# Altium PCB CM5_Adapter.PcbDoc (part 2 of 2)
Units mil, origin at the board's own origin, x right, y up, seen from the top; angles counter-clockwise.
Board outline 2180 x 1650 mil, 4 copper layers (Top Layer, Sig1, Sig2, Bottom Layer), stack 50.112 mil thick; 16 components, 251 nets, 1069 pads, 196 vias.
Unrouted connection lines stored in the file: 3.
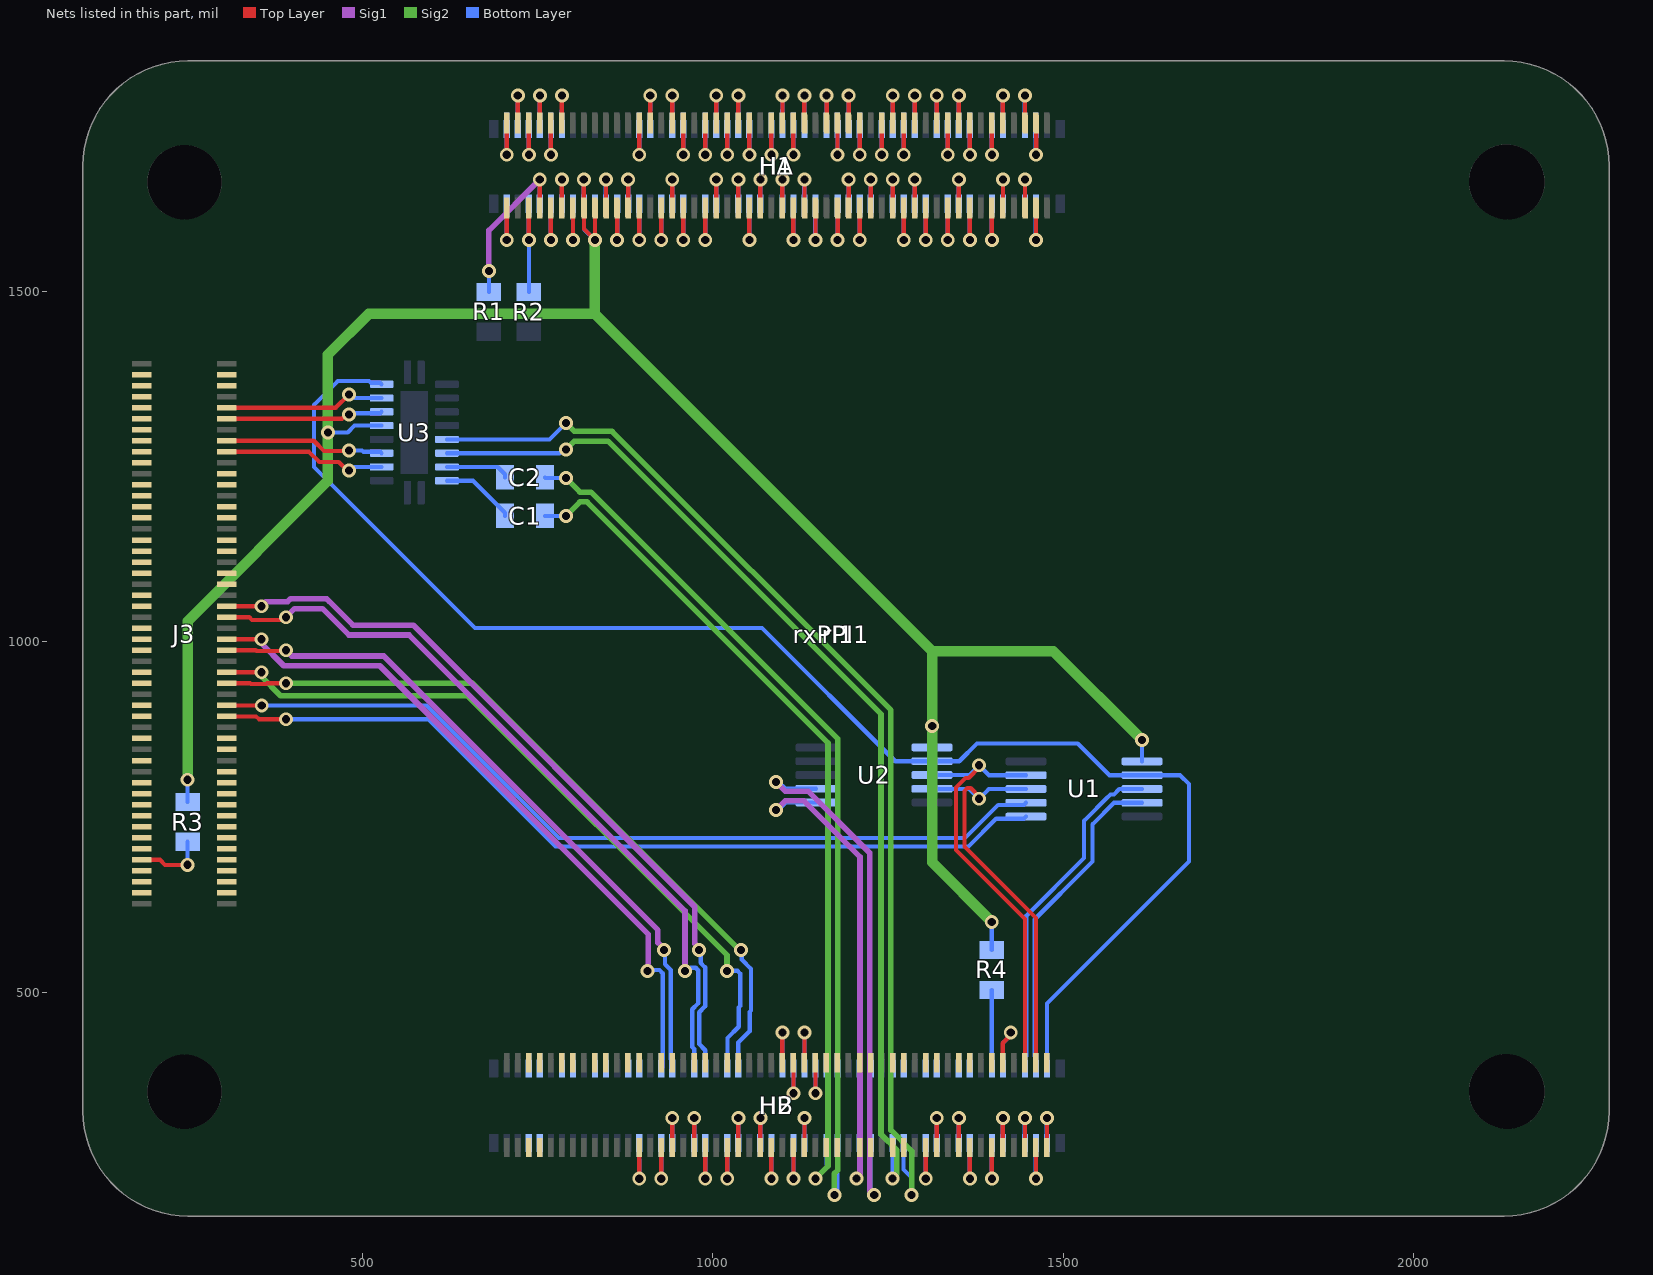
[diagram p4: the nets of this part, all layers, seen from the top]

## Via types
v1: diameter 19.68, hole 11.81, Top Layer to Bottom Layer, 196 vias

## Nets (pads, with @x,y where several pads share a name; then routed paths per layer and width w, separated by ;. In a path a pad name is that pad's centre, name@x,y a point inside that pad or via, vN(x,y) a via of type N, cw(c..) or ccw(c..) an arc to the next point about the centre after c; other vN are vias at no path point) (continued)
HDMI0_TX1_P: H2.76 HB.75 rPI1.176 rxPI1.176 | length 87.9
  Top Layer w6.3: v1(894.53,233.46) H2.76@894.53,276.9
  Bottom Layer w6.3: rPI1.176@894.34,277.83 894.34,260.9 894.53,260.72 v1(894.53,233.46)
HDMI0_TX2_N: H2.72 HB.71 rPI1.172 rxPI1.172 | length 87.9
  Top Layer w6.3: v1(926.02,233.46) H2.72@926.02,276.9
  Bottom Layer w6.3: rPI1.172@925.84,277.83 925.84,260.9 926.02,260.72 v1(926.02,233.46)
HDMI0_TX2_P: H2.70 HB.69 rPI1.170 rxPI1.170 | length 85.5
  Top Layer w6.3: H2.70@941.77,276.9 v1(941.77,320.08)
  Bottom Layer w6.3: rPI1.170@941.58,277.83 941.58,294.76 941.77,294.95 v1(941.77,320.08)
HDMI1_CEC: H2.49 HB.50 rPI1.149 rxPI1.149 | length 94.4
  Top Layer w6.3: H2.49@1099.06,399.09 1099.16,399.19 1099.16,442.03 v1(1099.25,442.13)
  Bottom Layer w6.3: HB.50@1099.25,390.88 v1(1099.25,442.13)
HDMI1_CLK_N: H2.66 HB.65 rPI1.166 rxPI1.166 | length 85.5
  Top Layer w6.3: H2.66@973.27,276.9 v1(973.27,320.08)
  Bottom Layer w6.3: rPI1.166@973.08,277.83 973.08,294.76 973.27,294.95 v1(973.27,320.08)
HDMI1_CLK_P: H2.64 HB.63 rPI1.164 rxPI1.164 | length 87.9
  Top Layer w6.3: v1(989.02,233.46) H2.64@989.02,276.9
  Bottom Layer w6.3: rPI1.164@988.83,277.83 988.83,260.9 989.02,260.72 v1(989.02,233.46)
HDMI1_HOTPLUG: H2.43 HB.44 rPI1.143 rxPI1.143 | length 79
  Top Layer w6.3: H2.43@1146.31,399.09 1146.4,399 1146.4,355.61 v1(1146.5,355.51)
  Bottom Layer w6.3: v1(1146.5,355.51) HB.44@1146.5,390.88
HDMI1_SCL: H2.47 HB.48 rPI1.147 rxPI1.147 | length 78
  Top Layer w6.3: v1(1115,355.51) H2.47@1115,398.16
  Bottom Layer w6.3: v1(1115,355.51) HB.48@1115,390.88
HDMI1_SDA: H2.45 HB.46 rPI1.145 rxPI1.145 | length 95.2
  Top Layer w6.3: H2.45@1130.75,398.16 v1(1130.75,442.13)
  Bottom Layer w6.3: HB.46@1130.75,390.88 v1(1130.75,442.13)
HDMI1_TX0_N: H2.60 HB.59 rPI1.160 rxPI1.160 | length 88.9
  Top Layer w6.3: H2.60@1020.32,277.83 1020.42,277.74 1020.42,233.56 v1(1020.51,233.46)
  Bottom Layer w6.3: rPI1.160@1020.32,277.83 1020.32,260.9 1020.51,260.72 v1(1020.51,233.46)
HDMI1_TX0_P: H2.58 HB.57 rPI1.158 rxPI1.158 | length 85.5
  Top Layer w6.3: H2.58@1036.26,276.9 v1(1036.26,320.08)
  Bottom Layer w6.3: rPI1.158@1036.07,277.83 1036.07,294.76 1036.26,294.95 v1(1036.26,320.08)
HDMI1_TX1_N: H2.54 HB.53 rPI1.154 rxPI1.154 | length 85.5
  Top Layer w6.3: H2.54@1067.76,276.9 v1(1067.76,320.08)
  Bottom Layer w6.3: rPI1.154@1067.57,277.83 1067.57,294.76 1067.76,294.95 v1(1067.76,320.08)
HDMI1_TX1_P: H2.52 HB.51 rPI1.152 rxPI1.152 | length 87.9
  Top Layer w6.3: v1(1083.5,233.46) H2.52@1083.5,276.9
  Bottom Layer w6.3: rPI1.152@1083.32,277.83 1083.32,260.9 1083.5,260.72 v1(1083.5,233.46)
HDMI1_TX2_N: H2.48 HB.47 rPI1.148 rxPI1.148 | length 94.2
  Top Layer w6.3: v1(1115,233.46) H2.48@1115,276.9
  Bottom Layer w6.3: v1(1115,233.46) HB.47@1115,284.18
HDMI1_TX2_P: H2.46 HB.45 rPI1.146 rxPI1.146 | length 79.1
  Top Layer w6.3: H2.46@1130.75,276.9 v1(1130.75,320.08)
  Bottom Layer w6.3: HB.45@1130.75,284.18 v1(1130.75,320.08)
I2C_SCL: J3.72 rxPI1.271
I2C_SDA: J3.70 rxPI1.269
NetC1_1: C1.1 U3.19 | length 106.5
  Bottom Layer w6: U3.19@620,1230.32 657.19,1230.32 703,1184.5 C1.1@703,1180
NetC2_1: C2.1 U3.18 | length 91.8
  Bottom Layer w6: U3.18@620,1250 692.56,1250 703,1239.56 C2.1@703,1235.06
NetH1_3: H1.3 HA.4 rPI1.3 rxPI1.3 | length 89.9
  Top Layer w6.3: v1(1461.46,1696.06) H1.3@1461.46,1739.81
  Bottom Layer w6.3: rPI1.3@1461.27,1742.17 1461.27,1696.25 v1(1461.46,1696.06)
NetH1_4: H1.4 HA.3 rPI1.4 rxPI1.4 | length 93.9
  Top Layer w6.3: rxPI1.4@1461.27,1620.91 1461.36,1620.81 1461.36,1574.11 v1(1461.46,1574.02)
  Bottom Layer w6.3: rPI1.4@1461.27,1620.91 1461.27,1574.2 v1(1461.46,1574.02)
NetH1_5: H1.5 HA.6 rPI1.5 rxPI1.5 | length 77.2
  Top Layer w6.3: rxPI1.5@1445.52,1742.17 1445.62,1742.26 1445.62,1780.62 v1(1445.71,1780.71)
  Bottom Layer w6.3: rPI1.5@1445.52,1742.17 1445.52,1780.52 v1(1445.71,1780.71)
NetH1_6: H1.6 HA.5 rPI1.6 rxPI1.6 | length 76.9
  Top Layer w6.3: H1.6@1445.71,1618.55 v1(1445.71,1660.63)
  Bottom Layer w6.3: HA.5@1445.71,1625.84 v1(1445.71,1660.63)
NetH1_9: H1.9 HA.10 rPI1.9 rxPI1.9 | length 77.2
  Top Layer w6.3: rxPI1.9@1414.03,1742.17 1414.12,1742.26 1414.12,1780.62 v1(1414.21,1780.71)
  Bottom Layer w6.3: rPI1.9@1414.03,1742.17 1414.03,1780.52 v1(1414.21,1780.71)
NetH1_10: H1.10 HA.9 rPI1.10 rxPI1.10 | length 76.9
  Top Layer w6.3: H1.10@1414.21,1618.55 v1(1414.21,1660.63)
  Bottom Layer w6.3: HA.9@1414.21,1625.84 v1(1414.21,1660.63)
NetH1_11: H1.11 HA.12 rPI1.11 rxPI1.11 | length 92.4
  Top Layer w6.3: rxPI1.11@1398.28,1742.17 1398.37,1742.07 1398.37,1696.16 v1(1398.46,1696.06)
  Bottom Layer w6.3: rPI1.11@1398.28,1742.17 1398.28,1696.25 v1(1398.46,1696.06)
NetH1_12: H1.12 HA.11 rPI1.12 rxPI1.12 | length 96.4
  Top Layer w6.3: v1(1398.46,1574.02) H1.12@1398.46,1618.55
  Bottom Layer w6.3: v1(1398.46,1574.02) HA.11@1398.46,1625.84
NetH1_15: H1.15 HA.16 rPI1.15 rxPI1.15 | length 80.2
  Top Layer w6.3: v1(1366.97,1696.06) H1.15@1366.97,1739.81
  Bottom Layer w6.3: v1(1366.97,1696.06) HA.16@1366.97,1732.53
NetH1_16: H1.16 HA.15 rPI1.16 rxPI1.16 | length 93.9
  Top Layer w6.3: rxPI1.16@1366.78,1620.91 1366.88,1620.81 1366.88,1574.11 v1(1366.97,1574.02)
  Bottom Layer w6.3: rPI1.16@1366.78,1620.91 1366.78,1574.2 v1(1366.97,1574.02)
NetH1_17: H1.17 HA.18 rPI1.17 rxPI1.17 | length 86.8
  Top Layer w6.3: rxPI1.17@1351.03,1742.17 1351.13,1742.26 1351.13,1780.62 v1(1351.22,1780.71)
  Bottom Layer w6.3: HA.18@1351.22,1732.53 v1(1351.22,1780.71)
NetH1_18: H1.18 HA.17 rPI1.18 rxPI1.18 | length 81.9
  Top Layer w6.3: H1.18@1351.22,1618.55 v1(1351.22,1660.63)
  Bottom Layer w6.3: rPI1.18@1351.03,1620.91 1351.03,1660.44 v1(1351.22,1660.63)
NetH1_19: H1.19 HA.20 rPI1.19 rxPI1.19 | length 89.9
  Top Layer w6.3: v1(1335.47,1696.06) H1.19@1335.47,1739.81
  Bottom Layer w6.3: rPI1.19@1335.29,1742.17 1335.29,1696.25 v1(1335.47,1696.06)
NetH1_20: H1.20 HA.19 rPI1.20 rxPI1.20 | length 91.5
  Top Layer w6.3: v1(1335.47,1574.02) H1.20@1335.47,1618.55
  Bottom Layer w6.3: rPI1.20@1335.29,1620.91 1335.29,1574.2 v1(1335.47,1574.02)
NetH1_21: H1.21 HA.22 rPI1.21 rxPI1.21 | length 77.2
  Top Layer w6.3: rxPI1.21@1319.54,1742.17 1319.63,1742.26 1319.63,1780.62 v1(1319.72,1780.71)
  Bottom Layer w6.3: rPI1.21@1319.54,1742.17 1319.54,1780.52 v1(1319.72,1780.71)
NetH1_24: H1.24 HA.23 rPI1.24 rxPI1.24 | length 91.5
  Top Layer w6.3: v1(1303.98,1574.02) H1.24@1303.98,1618.55
  Bottom Layer w6.3: rPI1.24@1303.79,1620.91 1303.79,1574.2 v1(1303.98,1574.02)
NetH1_25: H1.25 HA.26 rPI1.25 rxPI1.25 | length 76.7
  Top Layer w6.3: H1.25@1288.23,1742.35 v1(1288.23,1780.71)
  Bottom Layer w6.3: rPI1.25@1288.04,1742.17 1288.04,1759.1 ; 1288.23,1759.28 v1(1288.23,1780.71)
NetH1_26: H1.26 HA.25 rPI1.26 rxPI1.26 | length 79.6
  Top Layer w6.3: rxPI1.26@1288.04,1620.91 1288.13,1621 1288.13,1660.54 v1(1288.23,1660.63)
  Bottom Layer w6.3: rPI1.26@1288.04,1620.91 1288.04,1660.44 v1(1288.23,1660.63)
NetH1_27: H1.27 HA.28 rPI1.27 rxPI1.27 | length 92.4
  Top Layer w6.3: rxPI1.27@1272.29,1742.17 1272.39,1742.07 1272.39,1696.16 v1(1272.48,1696.06)
  Bottom Layer w6.3: rPI1.27@1272.29,1742.17 1272.29,1696.25 v1(1272.48,1696.06)
NetH1_28: H1.28 HA.27 rPI1.28 rxPI1.28 | length 91.5
  Top Layer w6.3: v1(1272.48,1574.02) H1.28@1272.48,1618.55
  Bottom Layer w6.3: rPI1.28@1272.29,1620.91 1272.29,1574.2 v1(1272.48,1574.02)
NetH1_29: H1.29 HA.30 rPI1.29 rxPI1.29 | length 76.7
  Top Layer w6.3: H1.29@1256.73,1742.35 v1(1256.73,1780.71)
  Bottom Layer w6.3: rPI1.29@1256.54,1742.17 1256.55,1759.1 ; 1256.73,1759.28 v1(1256.73,1780.71)
NetH1_30: H1.30 HA.29 rPI1.30 rxPI1.30 | length 79.6
  Top Layer w6.3: rxPI1.30@1256.55,1620.91 1256.64,1621 1256.64,1660.54 v1(1256.73,1660.63)
  Bottom Layer w6.3: rPI1.30@1256.54,1620.91 1256.55,1660.44 v1(1256.73,1660.63)
NetH1_31: H1.31 HA.32 rPI1.31 rxPI1.31 | length 92.4
  Top Layer w6.3: rxPI1.31@1240.8,1742.17 1240.89,1742.07 1240.89,1696.16 v1(1240.98,1696.06)
  Bottom Layer w6.3: rPI1.31@1240.8,1742.17 1240.8,1696.25 v1(1240.98,1696.06)
NetH1_34: H1.34 HA.33 rPI1.34 rxPI1.34 | length 81.9
  Top Layer w6.3: H1.34@1225.24,1618.55 v1(1225.24,1660.63)
  Bottom Layer w6.3: rPI1.34@1225.05,1620.91 1225.05,1660.44 v1(1225.24,1660.63)
NetH1_35: H1.35 HA.36 rPI1.35 rxPI1.35 | length 82.6
  Top Layer w6.3: rxPI1.35@1209.3,1742.17 1209.39,1742.07 1209.39,1696.16 v1(1209.49,1696.06)
  Bottom Layer w6.3: v1(1209.49,1696.06) HA.36@1209.49,1732.53
NetH1_36: H1.36 HA.35 rPI1.36 rxPI1.36 | length 93.9
  Top Layer w6.3: rxPI1.36@1209.3,1620.91 1209.39,1620.81 1209.39,1574.11 v1(1209.49,1574.02)
  Bottom Layer w6.3: rPI1.36@1209.3,1620.91 1209.3,1574.2 v1(1209.49,1574.02)
NetH1_37: H1.37 HA.38 rPI1.37 rxPI1.37 | length 86.8
  Top Layer w6.3: rxPI1.37@1193.55,1742.17 1193.65,1742.26 1193.65,1780.62 v1(1193.74,1780.71)
  Bottom Layer w6.3: HA.38@1193.74,1732.53 v1(1193.74,1780.71)
NetH1_38: H1.38 HA.37 rPI1.38 rxPI1.38 | length 79.6
  Top Layer w6.3: rxPI1.38@1193.55,1620.91 1193.65,1621 1193.65,1660.54 v1(1193.74,1660.63)
  Bottom Layer w6.3: rPI1.38@1193.55,1620.91 1193.55,1660.44 v1(1193.74,1660.63)
NetH1_39: H1.39 HA.40 rPI1.39 rxPI1.39 | length 92.4
  Top Layer w6.3: rxPI1.39@1177.81,1742.17 1177.9,1742.07 1177.9,1696.16 v1(1177.99,1696.06)
  Bottom Layer w6.3: rPI1.39@1177.8,1742.17 1177.81,1696.25 v1(1177.99,1696.06)
NetH1_40: H1.40 HA.39 rPI1.40 rxPI1.40 | length 91.5
  Top Layer w6.3: v1(1177.99,1574.02) H1.40@1177.99,1618.55
  Bottom Layer w6.3: rPI1.40@1177.8,1620.91 1177.81,1574.2 v1(1177.99,1574.02)
NetH1_41: H1.41 HA.42 rPI1.41 rxPI1.41 | length 89.1
  Top Layer w6.3: H1.41@1162.24,1739.81 v1(1162.24,1780.71)
  Bottom Layer w6.3: HA.42@1162.24,1732.53 v1(1162.24,1780.71)
NetH1_44: H1.44 HA.43 rPI1.44 rxPI1.44 | length 93.9
  Top Layer w6.3: rxPI1.44@1146.31,1620.91 1146.4,1620.81 1146.4,1574.11 v1(1146.5,1574.02)
  Bottom Layer w6.3: rPI1.44@1146.31,1620.91 1146.31,1574.2 v1(1146.5,1574.02)
NetH1_45: H1.45 HA.46 rPI1.45 rxPI1.45 | length 76.7
  Top Layer w6.3: H1.45@1130.56,1742.35 v1(1130.56,1780.71)
  Bottom Layer w6.3: rPI1.45@1130.37,1742.17 1130.37,1759.1 ; 1130.56,1759.28 v1(1130.56,1780.71)
NetH1_46: H1.46 HA.45 rPI1.46 rxPI1.46 | length 81.9
  Top Layer w6.3: H1.46@1130.75,1618.55 v1(1130.75,1660.63)
  Bottom Layer w6.3: rPI1.46@1130.56,1620.91 1130.56,1660.44 v1(1130.75,1660.63)
NetH1_47: H1.47 HA.48 rPI1.47 rxPI1.47 | length 82.7
  Top Layer w6.3: rxPI1.47@1114.81,1742.17 1114.91,1742.07 1114.91,1696.16 v1(1115,1696.06)
  Bottom Layer w6.3: rPI1.47@1114.81,1732.53 1114.81,1696.25 v1(1115,1696.06)
NetH1_48: H1.48 HA.47 rPI1.48 rxPI1.48 | length 93.9
  Top Layer w6.3: rxPI1.48@1114.81,1620.91 1114.91,1620.81 1114.91,1574.11 v1(1115,1574.02)
  Bottom Layer w6.3: rPI1.48@1114.81,1620.91 1114.81,1574.2 v1(1115,1574.02)
NetH1_49: H1.49 HA.50 rPI1.49 rxPI1.49 | length 76.7
  Top Layer w6.3: H1.49@1099.25,1742.35 v1(1099.25,1780.71)
  Bottom Layer w6.3: rPI1.49@1099.06,1742.17 1099.06,1759.1 ; 1099.25,1759.28 v1(1099.25,1780.71)
NetH1_50: H1.50 HA.49 rPI1.50 rxPI1.50 | length 79.6
  Top Layer w6.3: rxPI1.50@1099.06,1620.91 1099.16,1621 1099.16,1660.54 v1(1099.25,1660.63)
  Bottom Layer w6.3: rPI1.50@1099.06,1620.91 1099.06,1637.84 1099.25,1638.02 v1(1099.25,1660.63)
NetH1_51: H1.51 HA.52 rPI1.51 rxPI1.51 | length 92.4
  Top Layer w6.3: rxPI1.51@1083.32,1742.17 1083.41,1742.07 1083.41,1696.16 v1(1083.5,1696.06)
  Bottom Layer w6.3: rPI1.51@1083.32,1742.17 1083.32,1725.24 1083.5,1725.05 v1(1083.5,1696.06)
NetH1_54: H1.54 HA.53 rPI1.54 rxPI1.54 | length 79.6
  Top Layer w6.3: rxPI1.54@1067.57,1620.91 1067.66,1621 1067.66,1660.54 v1(1067.76,1660.63)
  Bottom Layer w6.3: rPI1.54@1067.57,1620.91 1067.57,1637.84 1067.76,1638.02 v1(1067.76,1660.63)
NetH1_55: H1.55 HA.56 rPI1.55 rxPI1.55 | length 80.2
  Top Layer w6.3: v1(1052.01,1696.06) H1.55@1052.01,1739.81
  Bottom Layer w6.3: v1(1052.01,1696.06) HA.56@1052.01,1732.53
NetH1_56: H1.56 HA.55 rPI1.56 rxPI1.56 | length 93.9
  Top Layer w6.3: rxPI1.56@1051.82,1620.91 1051.91,1620.81 1051.91,1574.11 v1(1052.01,1574.02)
  Bottom Layer w6.3: rPI1.56@1051.82,1620.91 1051.82,1603.98 1052.01,1603.79 v1(1052.01,1574.02)
NetH1_57: H1.57 HA.58 rPI1.57 rxPI1.57 | length 89.1
  Top Layer w6.3: H1.57@1036.26,1739.81 v1(1036.26,1780.71)
  Bottom Layer w6.3: HA.58@1036.26,1732.53 v1(1036.26,1780.71)
NetH1_58: H1.58 HA.57 rPI1.58 rxPI1.58 | length 79.6
  Top Layer w6.3: rxPI1.58@1036.07,1620.91 1036.17,1621 1036.17,1660.54 v1(1036.26,1660.63)
  Bottom Layer w6.3: rPI1.58@1036.07,1620.91 1036.07,1637.84 1036.26,1638.02 v1(1036.26,1660.63)
NetH1_59: H1.59 HA.60 rPI1.59 rxPI1.59 | length 82.6
  Top Layer w6.3: rxPI1.59@1020.32,1742.17 1020.42,1742.07 1020.42,1696.16 v1(1020.51,1696.06)
  Bottom Layer w6.3: v1(1020.51,1696.06) HA.60@1020.51,1732.53
NetH1_61: H1.61 HA.62 rPI1.61 rxPI1.61 | length 89.1
  Top Layer w6.3: H1.61@1004.76,1739.81 v1(1004.76,1780.71)
  Bottom Layer w6.3: HA.62@1004.76,1732.53 v1(1004.76,1780.71)
NetH1_62: H1.62 HA.61 rPI1.62 rxPI1.62 | length 81.9
  Top Layer w6.3: H1.62@1004.76,1618.55 v1(1004.76,1660.63)
  Bottom Layer w6.3: rPI1.62@1004.58,1620.91 1004.58,1637.84 1004.76,1638.02 v1(1004.76,1660.63)
NetH1_63: H1.63 HA.64 rPI1.63 rxPI1.63 | length 82.6
  Top Layer w6.3: rxPI1.63@988.83,1742.17 988.92,1742.07 988.92,1696.16 v1(989.02,1696.06)
  Bottom Layer w6.3: v1(989.02,1696.06) HA.64@989.02,1732.53
NetH1_64: H1.64 HA.63 rPI1.64 rxPI1.64 | length 91.5
  Top Layer w6.3: v1(989.02,1574.02) H1.64@989.02,1618.55
  Bottom Layer w6.3: rPI1.64@988.83,1620.91 988.83,1603.98 989.02,1603.79 v1(989.02,1574.02)
NetH1_67: H1.67 HA.68 rPI1.67 rxPI1.67 | length 82.6
  Top Layer w6.3: rxPI1.67@957.33,1742.17 957.43,1742.07 957.43,1696.16 v1(957.52,1696.06)
  Bottom Layer w6.3: v1(957.52,1696.06) HA.68@957.52,1732.53
NetH1_68: H1.68 HA.67 rPI1.68 rxPI1.68 | length 98.8
  Top Layer w6.3: rxPI1.68@957.33,1620.91 957.43,1620.81 957.43,1574.11 v1(957.52,1574.02)
  Bottom Layer w6.3: v1(957.52,1574.02) HA.67@957.52,1625.84
NetH1_69: H1.69 HA.70 rPI1.69 rxPI1.69 | length 89.1
  Top Layer w6.3: H1.69@941.77,1739.81 v1(941.77,1780.71)
  Bottom Layer w6.3: HA.70@941.77,1732.53 v1(941.77,1780.71)
NetH1_70: H1.70 HA.69 rPI1.70 rxPI1.70 | length 76.9
  Top Layer w6.3: H1.70@941.77,1618.55 v1(941.77,1660.63)
  Bottom Layer w6.3: HA.69@941.77,1625.84 v1(941.77,1660.63)
NetH1_72: H1.72 HA.71 rPI1.72 rxPI1.72 | length 91.5
  Top Layer w6.3: v1(926.02,1574.02) H1.72@926.02,1618.55
  Bottom Layer w6.3: rPI1.72@925.84,1620.91 925.84,1603.98 926.02,1603.79 v1(926.02,1574.02)
NetH1_73: H1.73 HA.74 rPI1.73 rxPI1.73 | length 77.2
  Top Layer w6.3: rxPI1.73@910.09,1742.17 910.18,1742.26 910.18,1780.62 v1(910.28,1780.71)
  Bottom Layer w6.3: rPI1.73@910.09,1742.17 910.09,1759.1 910.28,1759.28 v1(910.28,1780.71)
NetH1_75: H1.75 HA.76 rPI1.75 rxPI1.75 | length 92.4
  Top Layer w6.3: rxPI1.75@894.34,1742.17 894.43,1742.07 894.43,1696.16 v1(894.53,1696.06)
  Bottom Layer w6.3: rPI1.75@894.34,1742.17 894.34,1725.24 894.53,1725.05 v1(894.53,1696.06)
NetH1_76: H1.76 HA.75 rPI1.76 rxPI1.76 | length 98.8
  Top Layer w6.3: rxPI1.76@894.34,1620.91 894.43,1620.81 894.43,1574.11 v1(894.53,1574.02)
  Bottom Layer w6.3: v1(894.53,1574.02) HA.75@894.53,1625.84
NetH1_78: H1.78 HA.77 rPI1.78 rxPI1.78 | length 79.6
  Top Layer w6.3: rxPI1.78@878.59,1620.91 878.69,1621 878.69,1660.54 v1(878.78,1660.63)
  Bottom Layer w6.3: rPI1.78@878.59,1620.91 878.59,1637.84 878.78,1638.02 v1(878.78,1660.63)
NetH1_80: H1.80 HA.79 rPI1.80 rxPI1.80 | length 96.4
  Top Layer w6.3: v1(863.03,1574.02) H1.80@863.03,1618.55
  Bottom Layer w6.3: v1(863.03,1574.02) HA.79@863.03,1625.84
NetH1_82: H1.82 HA.81 rPI1.82 rxPI1.82 | length 81.9
  Top Layer w6.3: v1(847.1,1660.63) 847.19,1660.54 847.19,1618.65 H1.82@847.28,1618.55
  Bottom Layer w6.3: rPI1.82@847.1,1620.91 v1(847.1,1660.63)
NetH1_88: H1.88 HA.87 rPI1.88 rxPI1.88 | length 91.5
  Top Layer w6.3: v1(800.04,1574.02) H1.88@800.04,1618.55
  Bottom Layer w6.3: rPI1.88@799.85,1620.91 799.85,1603.98 800.04,1603.79 v1(800.04,1574.02)
NetH1_89: H1.89 HA.90 rPI1.89 rxPI1.89 | length 77.2
  Top Layer w6.3: rxPI1.89@784.1,1742.17 784.2,1742.26 784.2,1780.62 v1(784.29,1780.71)
  Bottom Layer w6.3: rPI1.89@784.1,1742.17 784.1,1759.1 784.29,1759.28 v1(784.29,1780.71)
NetH1_90: H1.90 HA.89 rPI1.90 rxPI1.90 | length 79.6
  Top Layer w6.3: rxPI1.90@784.1,1620.91 784.2,1621 784.2,1660.54 v1(784.29,1660.63)
  Bottom Layer w6.3: rPI1.90@784.1,1620.91 784.1,1637.84 784.29,1638.02 v1(784.29,1660.63)
NetH1_91: H1.91 HA.92 rPI1.91 rxPI1.91 | length 89.9
  Top Layer w6.3: v1(768.54,1696.06) H1.91@768.54,1739.81
  Bottom Layer w6.3: rPI1.91@768.36,1742.17 768.36,1725.24 768.54,1725.05 v1(768.54,1696.06)
NetH1_92: H1.92 HA.91 rPI1.92 rxPI1.92 | length 93.9
  Top Layer w6.3: rxPI1.92@768.36,1620.91 768.45,1620.81 768.45,1574.11 v1(768.54,1574.02)
  Bottom Layer w6.3: rPI1.92@768.36,1620.91 768.36,1603.98 768.54,1603.79 v1(768.54,1574.02)
NetH1_93: H1.93 HA.94 rPI1.93 rxPI1.93 | length 77.2
  Top Layer w6.3: rxPI1.93@752.61,1742.17 752.7,1742.26 752.7,1780.62 v1(752.8,1780.71)
  Bottom Layer w6.3: rPI1.93@752.61,1742.17 752.61,1759.1 752.8,1759.28 v1(752.8,1780.71)
NetH1_94: H1.94 HA.93 R1.1 rPI1.94 rxPI1.94 | length 270.2
  Top Layer w6.3: rxPI1.94@752.61,1620.91 v1(752.61,1660.63)
  Sig1 w8: v1(679.96,1530) 679.96,1587.98 v1(752.61,1660.63)
  Bottom Layer w6: R1.1@679.96,1500 v1(679.96,1530)
  Bottom Layer w6.3: rPI1.94@752.61,1620.91 v1(752.61,1660.63)
NetH1_95: H1.95 HA.96 rPI1.95 rxPI1.95 | length 92.4
  Top Layer w6.3: rxPI1.95@736.86,1742.17 736.95,1742.07 736.95,1696.16 v1(737.05,1696.06)
  Bottom Layer w6.3: rPI1.95@736.86,1742.17 736.86,1725.24 737.05,1725.05 v1(737.05,1696.06)
NetH1_96: H1.96 HA.95 R2.1 rPI1.96 rxPI1.96 | length 168
  Top Layer w6.3: rxPI1.96@736.86,1620.91 736.95,1620.81 736.95,1574.11 v1(737.05,1574.02)
  Bottom Layer w6: R2.1@737.05,1500 v1(737.05,1574.02)
  Bottom Layer w6.3: rPI1.96@736.86,1620.91 736.86,1603.98 737.05,1603.79 v1(737.05,1574.02)
NetH1_97: H1.97 HA.98 rPI1.97 rxPI1.97 | length 76.7
  Top Layer w6.3: H1.97@721.3,1742.35 v1(721.3,1780.71)
  Bottom Layer w6.3: rPI1.97@721.11,1742.17 721.11,1759.1 ; 721.3,1759.28 v1(721.3,1780.71)
NetH1_99: H1.99 HA.100 rPI1.99 rxPI1.99 | length 92.4
  Top Layer w6.3: rxPI1.99@705.36,1742.17 705.46,1742.07 705.46,1696.16 v1(705.55,1696.06)
  Bottom Layer w6.3: rPI1.99@705.36,1742.17 705.36,1725.24 705.55,1725.05 v1(705.55,1696.06)
NetH1_100: H1.100 HA.99 rPI1.100 rxPI1.100 | length 93.9
  Top Layer w6.3: rxPI1.100@705.36,1620.91 705.46,1620.81 705.46,1574.11 v1(705.55,1574.02)
  Bottom Layer w6.3: rPI1.100@705.36,1620.91 705.36,1603.98 705.55,1603.79 v1(705.55,1574.02)
NetH2_11: H2.11 rxPI1.111
NetH2_15: H2.15 rxPI1.115
NetH2_17: H2.17 rxPI1.117
NetH2_21: H2.21 rxPI1.121
NetH2_23: H2.23 rxPI1.123
NetH2_27: H2.27 rxPI1.127
NetH2_28: H2.28 rxPI1.128
NetH2_29: H2.29 rxPI1.129
NetH2_30: H2.30 rxPI1.130
NetH2_33: H2.33 rxPI1.133
NetH2_34: H2.34 rxPI1.134
NetH2_35: H2.35 rxPI1.135
NetH2_36: H2.36 rxPI1.136
NetH2_39: H2.39 rxPI1.139
NetH2_40: H2.40 rxPI1.140
NetH2_41: H2.41 rxPI1.141
NetH2_42: H2.42 rxPI1.142
NetH2_57: H2.57 rxPI1.157
NetH2_59: H2.59 rxPI1.159
NetH2_63: H2.63 rxPI1.163
NetH2_65: H2.65 rxPI1.165
NetH2_69: H2.69 rxPI1.169
NetH2_71: H2.71 rxPI1.171
NetH2_75: H2.75 rxPI1.175
NetH2_77: H2.77 rxPI1.177
NetH2_81: H2.81 rxPI1.181
NetH2_83: H2.83 rxPI1.183
NetH2_87: H2.87 rxPI1.187
NetH2_89: H2.89 rxPI1.189
NetH2_93: H2.93 rxPI1.193
NetH2_94: H2.94 rxPI1.194
NetH2_95: H2.95 rxPI1.195
NetH2_96: H2.96 rxPI1.196
NetHB_12: HB.12 R4.2 rPI1.111 | length 103.9
  Bottom Layer w6: rPI1.111@1398.28,399.09 R4.2@1398.28,503
NetHB_16: HB.16 rPI1.115
NetHB_18: HB.18 rPI1.117
NetHB_22: HB.22 rPI1.121
NetHB_24: HB.24 rPI1.123
NetHB_28: HB.28 rPI1.127
NetHB_30: HB.30 rPI1.129
NetHB_34: HB.34 rPI1.133
NetHB_36: HB.36 rPI1.135
NetHB_40: HB.40 rPI1.139
NetHB_42: HB.42 rPI1.141
NetHB_76: HB.76 rPI1.175
NetHB_78: HB.78 rPI1.177
NetHB_82: HB.82 rPI1.181
NetHB_84: HB.84 rPI1.183
NetHB_88: HB.88 rPI1.187
NetHB_90: HB.90 rPI1.189
NetHB_93: HB.93 rPI1.194
NetHB_94: HB.94 rPI1.193
NetHB_95: HB.95 rPI1.196
NetHB_96: HB.96 rPI1.195
NetJ3_3: J3.3 rxPI1.204
NetJ3_4: J3.4 rxPI1.203
NetJ3_5: J3.5 rxPI1.206
NetJ3_6: J3.6 rxPI1.205
NetJ3_7: J3.7 rxPI1.208
NetJ3_9: J3.9 rxPI1.210
NetJ3_11: J3.11 rxPI1.212
NetJ3_13: J3.13 rxPI1.214
NetJ3_15: J3.15 rxPI1.216
NetJ3_17: J3.17 rxPI1.218
NetJ3_19: J3.19 rxPI1.220
NetJ3_22: J3.22 rxPI1.221
NetJ3_23: J3.23 rxPI1.224
NetJ3_24: J3.24 rxPI1.223
NetJ3_25: J3.25 rxPI1.226
NetJ3_27: J3.27 rxPI1.228
NetJ3_28: J3.28 rxPI1.227
NetJ3_29: J3.29 rxPI1.230
NetJ3_30: J3.30 rxPI1.229
NetJ3_33: J3.33 rxPI1.234
NetJ3_34: J3.34 rxPI1.233
NetJ3_35: J3.35 rxPI1.236
NetJ3_36: J3.36 rxPI1.235
NetJ3_37: J3.37 rxPI1.238
NetJ3_39: J3.39 rxPI1.240
NetJ3_40: J3.40 rxPI1.239
NetJ3_42: J3.42 rxPI1.241
NetJ3_43: J3.43 rxPI1.244
NetJ3_45: J3.45 rxPI1.246
NetJ3_49: J3.49 rxPI1.250
NetJ3_51: J3.51 rxPI1.252
NetJ3_53: J3.53 rxPI1.254
NetJ3_57: J3.57 rxPI1.258
NetJ3_59: J3.59 rxPI1.260
NetJ3_63: J3.63 rxPI1.264
NetJ3_65: J3.65 rxPI1.266
NetJ3_69: J3.69 rxPI1.270
NetJ3_73: J3.73 rxPI1.274
NetJ3_76: J3.76 rxPI1.275
NetJ3_77: J3.77 rxPI1.278
NetJ3_78: J3.78 rxPI1.277
NetJ3_79: J3.79 rxPI1.280
NetJ3_80: J3.80 rxPI1.279
NetJ3_81: J3.81 rxPI1.282
NetJ3_82: J3.82 rxPI1.281
NetJ3_83: J3.83 rxPI1.284
NetJ3_84: J3.84 rxPI1.283
NetJ3_85: J3.85 rxPI1.286
NetJ3_86: J3.86 rxPI1.285
NetJ3_87: J3.87 rxPI1.288
NetJ3_88: J3.88 rxPI1.287
NetJ3_89: J3.89 rxPI1.290
NetJ3_90: J3.90 rxPI1.289
NetJ3_91: J3.91 R3.2 rxPI1.292 | length 99.7
  Top Layer w6: J3.91@184.13,688.95 210,688.95 217.32,681.62 v1@247.81,681.62
  Bottom Layer w6: v1(249.47,681.62) R3.2@249.47,714.62
NetJ3_92: J3.92 rxPI1.291
NetJ3_93: J3.93 rxPI1.294
NetJ3_94: J3.94 rxPI1.293
NetJ3_95: J3.95 rxPI1.296
NetJ3_96: J3.96 rxPI1.295
NetJ3_97: J3.97 rxPI1.298
NetJ3_98: J3.98 rxPI1.297
PCIe_CLK_N: H2.12 HB.11 rPI1.112 rxPI1.112 | length 88.9
  Top Layer w6.3: H2.12@1398.28,277.83 1398.37,277.74 1398.37,233.56 v1(1398.46,233.46)
  Bottom Layer w6.3: rPI1.112@1398.28,277.83 1398.28,233.65 v1(1398.46,233.46)
PCIe_CLK_nREQ: H2.2 HB.1 rPI1.102 rxPI1.102 | length 84.6
  Top Layer w6.3: H2.2@1477.02,277.83 1477.11,277.93 1477.11,319.99 v1(1477.2,320.08)
  Bottom Layer w6.3: rPI1.102@1477.02,277.83 1477.02,319.89 v1(1477.2,320.08)
PCIe_CLK_P: H2.10 HB.9 rPI1.110 rxPI1.110 | length 84.6
  Top Layer w6.3: H2.10@1414.03,277.83 1414.12,277.93 1414.12,319.99 v1(1414.21,320.08)
  Bottom Layer w6.3: rPI1.110@1414.03,277.83 1414.03,319.89 v1(1414.21,320.08)
PCIe_nRST: H2.9 HB.10 rPI1.109 rxPI1.109 | length 95.5
  Top Layer w6.3: H2.9@1414.12,399.19 1414.03,399.28 1414.03,427.1 1425.43,438.5 v1(1425.43,442.13)
  Bottom Layer w6.3: rPI1.109@1414.03,399.09 1414.21,399.28 1414.21,427.28 1425.43,438.5 v1(1425.43,442.13)
PCIe_RX_N: H2.18 HB.17 rPI1.118 rxPI1.118 | length 84.6
  Top Layer w6.3: H2.18@1351.03,277.83 1351.13,277.93 1351.13,319.99 v1(1351.22,320.08)
  Bottom Layer w6.3: rPI1.118@1351.03,277.83 1351.03,319.89 v1(1351.22,320.08)
PCIe_RX_P: H2.16 HB.15 rPI1.116 rxPI1.116 | length 88.9
  Top Layer w6.3: H2.16@1366.78,277.83 1366.88,277.74 1366.88,233.56 v1(1366.97,233.46)
  Bottom Layer w6.3: rPI1.116@1366.78,277.83 1366.78,233.65 v1(1366.97,233.46)
PCIe_TX_N: H2.24 HB.23 rPI1.124 rxPI1.124 | length 88.9
  Top Layer w6.3: H2.24@1303.79,277.83 1303.88,277.74 1303.88,233.56 v1(1303.98,233.46)
  Bottom Layer w6.3: rPI1.124@1303.79,277.83 1303.79,233.65 v1(1303.98,233.46)
PCIe_TX_P: H2.22 HB.21 rPI1.122 rxPI1.122 | length 84.6
  Top Layer w6.3: H2.22@1319.54,277.83 1319.63,277.93 1319.63,319.99 v1(1319.72,320.08)
  Bottom Layer w6.3: rPI1.122@1319.54,277.83 1319.54,319.89 v1(1319.72,320.08)
Res104: H2.4 HB.3 rPI1.104 rxPI1.104 | length 88.9
  Top Layer w6.3: H2.4@1461.27,277.83 1461.36,277.74 1461.36,233.56 v1(1461.46,233.46)
  Bottom Layer w6.3: rPI1.104@1461.27,277.83 1461.27,233.65 v1(1461.46,233.46)
Res106: H2.6 HB.5 rPI1.106 rxPI1.106 | length 84.6
  Top Layer w6.3: H2.6@1445.52,277.83 1445.62,277.93 1445.62,319.99 v1(1445.71,320.08)
  Bottom Layer w6.3: rPI1.106@1445.52,277.83 1445.52,319.89 v1(1445.71,320.08)
USB20_HOST_D_N: J3.66 rxPI1.265 U1.6 | length 1236.3
  Top Layer w6: J3.66@305.39,893.67 347.43,893.67 351.36,889.73 v1(390,889.73)
  Bottom Layer w6: v1(390,889.73) 593.29,889.73 775.03,708 1365.01,708 1404.64,747.63 1444.13,747.63 U1.6@1447.13,750.63
USB20_HOST_D_P: J3.64 rxPI1.263 U1.7 | length 1241
  Top Layer w6: J3.64@305.39,909.42 v1(355.5,909.42)
  Bottom Layer w6: v1(355.5,909.42) 590.58,909.42 780,720 1360.04,720 1407.35,767.32 1444.13,767.32 U1.7@1447.13,770.32
USB30_D_N: HB.35 rPI1.136 U2.6 | length 727.5
  Sig1 w8: v1(1090,760) 1103,773 1130,773 1210,693 1210,238.69 v1(1204.96,233.65)
  Bottom Layer w6: v1(1090,760) 1093.7,760 1104.33,770.63 U2.6@1147.13,770.63 ; v1(1204.96,233.65) 1204.96,237.35 1209.3,241.7 rPI1.136@1209.3,277.83
USB30_D_P: HB.33 rPI1.134 U2.7 | length 798.4
  Sig1 w8: v1(1090,800) 1103,787 1135.8,787 1224,698.8 1224,216.16 v1(1230.16,210)
  Bottom Layer w6: v1(1090,800) 1093.7,800 1103.39,790.32 U2.7@1147.13,790.32 ; rPI1.134@1225.05,277.83 1225.05,218.82 1230.16,213.7 v1(1230.16,210)
USB30_RX1_N: HB.27 rPI1.128 U3.16 | length 1591.2
  Sig2 w8: v1(790,1312.89) 802.05,1300.85 855.8,1300.85 1254,902.65 1254,302.66 1283.7,272.96 v1(1283.7,210)
  Bottom Layer w6: U3.16@620,1289.37 766.48,1289.37 v1(790,1312.89) ; rPI1.128@1272.29,277.83 1272.29,246.55 1283.7,235.14 v1(1283.7,210)
USB30_RX1_P: HB.29 rPI1.130 U3.17 | length 1507.9
  Sig2 w8: v1(790,1274.8) 802.05,1286.85 850,1286.85 1240,896.85 1240,296.86 1262.58,274.28 1262.58,239.69 v1(1256.54,233.65)
  Bottom Layer w6: U3.17@620,1269.68 781.18,1269.68 786.3,1274.8 v1(790,1274.8) ; v1(1256.54,233.65) rPI1.130@1256.54,277.83
USB30_TX1_N: C2.2 HB.39 rPI1.140 | length 1296.2
  Sig2 w8: v1(790,1234.15) 810.08,1214.08 825.8,1214.08 1178.34,861.54 1178.34,245.7 1173.46,240.82 v1(1173.46,210)
  Bottom Layer w6: C2.2@760,1235.06 760.9,1234.15 v1(790,1234.15) ; v1(1173.46,210) 1173.46,213.7 1177.8,218.04 rPI1.140@1177.8,277.83
USB30_TX1_P: C1.2 HB.41 rPI1.142 | length 1235.9
  Sig2 w8: v1(790,1180) 810.08,1200.08 820,1200.08 1164.34,855.74 1164.34,251.49 v1(1146.31,233.46)
  Bottom Layer w6: C1.2@760,1180 v1(790,1180) ; v1(1146.31,233.46) 1162.06,249.21 rPI1.142@1162.06,277.83
USB31_D_N: HB.66 J3.48 rPI1.165 rxPI1.247 | length 1095.2
  Top Layer w6: J3.48@305.39,1035.4 337.65,1035.4 341.74,1031.31 382.2,1031.31 386.3,1035.4 v1(390,1035.4)
  Sig1 w8: v1(390,1035.4) 402.3,1047.7 442.3,1047.7 475.9,1014.1 480,1010 566,1010 960,616 v1(960,530)
  Bottom Layer w6: v1(960,530) 963.7,530 968.38,534.67 975.33,534.67 978.84,531.16 978.84,483.83 970.34,475.32 970.34,421.43 973.27,418.5 973.27,410.37 HB.66@973.27,390.88
USB31_D_P: HB.64 J3.46 rPI1.163 rxPI1.245 | length 1099.4
  Top Layer w6: J3.46@305.39,1051.15 v1(355,1051.15)
  Sig1 w8: v1(355,1051.15) 361.45,1057.6 392.4,1057.6 396.5,1061.7 448.1,1061.7 452.2,1057.6 485.8,1024 571.8,1024 974,621.8 974,569.16 980,563.16 v1(980,560)
  Bottom Layer w6: v1(980,560) 982.4,557.6 982.4,541.74 988.84,535.3 988.84,479.69 980.34,471.18 980.34,425.57 989.02,416.89 HB.64@989.02,390.88
USB31_RX_N: HB.58 J3.60 rPI1.157 rxPI1.259 | length 1067.8
  Top Layer w6: J3.60@305.39,940.92 338.53,940.92 339.62,939.82 361.98,939.82 363.07,940.92 v1(390,940.92)
  Sig2 w8: v1(390,940.92) 656.94,940.92 1037.86,560 v1(1040,560)
  Bottom Layer w6: rPI1.157@1036.07,399.09 1036.17,399.19 1036.17,427.7 1052.4,443.94 1052.4,471.5 1054.4,473.5 1054.4,533.1 1041.08,546.43 1041.08,558.92 v1(1040,560)
USB31_RX_P: HB.60 J3.58 rPI1.159 rxPI1.257 | length 1072
  Top Layer w6: J3.58@305.39,956.66 v1(355,956.66)
  Sig2 w8: v1(355,956.66) 355,950.68 382.61,923.07 649.55,923.07 1020,552.62 v1(1020,530)
  Bottom Layer w6: v1(1020,530) 1020.43,530.43 1035.07,530.43 1038.84,526.66 1038.84,479.94 1036.84,477.94 1036.84,450.39 1020.61,434.15 1020.61,390.97 HB.60@1020.51,390.88
USB31_TX_N: HB.70 J3.54 rPI1.169 rxPI1.253 | length 988.5
  Top Layer w6: J3.54@305.39,988.16 346.93,988.16 348.02,987.07 388.91,987.07 v1(390,988.16)
  Sig1 w8: v1(390,988.16) 398.16,980 529.8,980 921.34,588.46 921.34,570.53 930,561.87 v1(930,560)
  Bottom Layer w6: v1(930,560) 931.58,558.42 931.58,539.73 939.66,531.65 939.66,404.38 940.24,403.8 940.24,392.4 HB.70@941.77,390.88
USB31_TX_P: HB.72 J3.52 rPI1.171 rxPI1.251 | length 994.3
  Top Layer w6: J3.52@305.39,1003.91 v1(355,1003.91)
  Sig1 w8: v1(355,1003.91) 355,997.93 386.93,966 524,966 907.34,582.66 907.34,531.03 v1(906.31,530)
  Bottom Layer w6: v1(906.31,530) 907.89,531.58 923.43,531.58 928.13,526.87 928.13,404.38 927.55,403.8 927.55,392.4 HB.72@926.02,390.88
USB_C_D_N: H2.3 rxPI1.103 U1.8 U2.4 | length 607
  Top Layer w6: v1(1380,776.14) 1380,779.4 1368.18,791.21 1363.21,791.21 1359.24,787.24 1359.24,707.73 1461.27,605.7 H2.3@1461.27,399.09
  Bottom Layer w6: U2.4@1312.87,790.32 1313.03,790.16 1365.98,790.16 v1(1380,776.14) 1394.02,790.16 1446.97,790.16 U1.8@1447.13,790
USB_C_D_P: H2.5 rxPI1.105 U1.9 U2.3 | length 627.5
  Top Layer w6: v1(1380,823.86) 1380,820.6 1365.26,805.87 1360.9,805.87 1347.24,792.21 1347.24,702.76 1351.51,698.49 1445.52,604.48 H2.5@1445.52,399.09
  Bottom Layer w6: U2.3@1312.87,810 1366.14,810 v1(1380,823.86) 1394.17,809.68 U1.9@1447.13,809.68
USB_C_RX1_N: J3.12 rxPI1.211 U3.7 | length 225.4
  Top Layer w6: J3.12@305.39,1318.87 470.26,1318.87 476.3,1324.9 v1(480,1324.9)
  Bottom Layer w6: v1(480,1324.9) 481.92,1326.82 524.77,1326.82 U3.7@526.69,1328.74
USB_C_RX1_P: J3.10 rxPI1.209 U3.8 | length 231.3
  Top Layer w6: J3.10@305.39,1334.62 461.07,1334.62 v1(480,1353.54)
  Bottom Layer w6: v1(480,1353.54) 483.7,1353.54 488.82,1348.43 U3.8@526.69,1348.43
USB_C_TX1_N: J3.18 rxPI1.217 U3.3 | length 234.5
  Top Layer w6: J3.18@305.39,1271.62 423.15,1271.62 437.72,1257.06 465.53,1257.06 477.7,1244.88 v1(480,1244.88)
  Bottom Layer w6: v1(480,1244.88) 483.7,1244.88 488.82,1250 U3.3@526.69,1250
USB_C_TX1_P: J3.16 rxPI1.215 U3.4 | length 229.2
  Top Layer w6: J3.16@305.39,1287.37 429.68,1287.37 444.25,1272.8 479.28,1272.8 v1(480,1273.52)
  Bottom Layer w6: v1(480,1273.52) 498.84,1273.52 500.76,1271.6 524.78,1271.6 U3.4@526.69,1269.68
USB_OTG_D_N: HB.4 rPI1.103 U1.4 | length 467.2
  Bottom Layer w6: HB.4@1461.46,390.88 1461.46,406.87 1459.58,408.74 1459.58,604.01 1534.97,679.4 1542,686.43 1542,739.56 1572.76,770.32 U1.4@1612.87,770.32
USB_OTG_D_P: HB.6 rPI1.105 U1.3 | length 490.3
  Bottom Layer w6: HB.6@1445.71,390.88 1445.71,406.87 1447.58,408.74 1447.58,608.98 1530,691.4 1530,744.53 1533.51,748.04 1561.51,776.04 1567.79,782.32 1572.66,782.32 1580.35,790 U1.3@1612.87,790
USB_OTG_ID: H2.1 HB.2 rPI1.101 rxPI1.101 U1.2 U2.2 U3.9 | length 2150.1
  Bottom Layer w6: U3.9@526.69,1368.11 524.57,1370.23 511.48,1370.23 508.86,1372.85 464.11,1372.85 430,1338.74 430,1250 660,1020 1070,1020 1260.32,829.68 U2.2@1312.87,829.68 1351.81,829.68 1377.01,854.88 1521.02,854.88 1566.22,809.68 U1.2@1612.87,809.68 1667.24,809.68 1680,796.93 1680,686.43 1477.2,483.64 HB.2@1477.2,390.88
VCC_3V3_S3: H1.84 H1.86 HA.83 HA.85 R3.1 R4.1 rPI1.84 rPI1.86 rxPI1.84 rxPI1.86 U1.1 U2.1 U3.6 | length 3160.4
  Top Layer w6: rxPI1.86@815.6,1620.91 815.6,1589.76 v1(831.35,1574.02) rxPI1.84@831.35,1620.91
  Top Layer w6.3: rxPI1.86@815.6,1620.91 v1(815.6,1660.63)
  Sig2 w15: v1(249.47,803.12) 249.47,1029.47 450,1230 v1(450,1299.21) 450,1410 508.65,1468.65 831.35,1468.65 ; v1(831.35,1574.02) 831.35,1468.65 ; v1(1398.28,600) 1313.03,685.25 v1(1313.03,880) 1313.03,986.97 ; v1(1612.87,860) 1485.91,986.97 1313.03,986.97 ; 831.35,1468.65 1313.03,986.97
  Bottom Layer w6: R3.1@249.47,771.62 v1(249.47,803.12) ; v1(450,1299.21) 478.31,1299.21 488.15,1309.06 U3.6@526.69,1309.06 ; HA.85@815.79,1625.84 815.79,1589.58 v1(831.35,1574.02) 831.54,1574.2 HA.83@831.54,1625.84 ; U2.1@1312.87,849.37 1313.03,849.53 v1(1313.03,880) ; R4.1@1398.28,560 v1(1398.28,600) ; U1.1@1612.87,829.37 v1(1612.87,860)
  Bottom Layer w6.3: rPI1.86@815.6,1620.91 v1(815.6,1660.63)
pads on no net: HA.S1 HA.S2 HA.S3 HA.S4 HB.S1 HB.S2 HB.S3 HB.S4 rPI1.Un1 rPI1.Un2 rPI1.Un3 rPI1.Un4 rxPI1. rxPI1.Un2 rxPI1.Un3 rxPI1.Un4 U2.8 U2.9 U3.1 U3.10 U3.12 U3.13 U3.14 U3.15

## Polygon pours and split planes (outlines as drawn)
GND on Sig2 "NONET_L01_P-001" (solid, remove dead copper, pour order 9): 250,1830 2130,1830 cw(c2130,1680) 2280,1680 2280,330 cw(c2130,330) 2130,180 250,180 cw(c250,330) 100,330 100,1680 cw(c250,1680)
5VDC_BUS on Sig2 "NONET_L01_P-001" (solid, pour order 4): 800.04,1800 784.29,1784.25 784.29,1695.75 800.04,1680 863.03,1680 863.03,1680.31 894.53,1711.81 894.53,1785.47 880,1800
GND on Top Layer "NONET_L01_P-001" (solid, remove dead copper, pour order 5): 250,1830 2130,1830 cw(c2130,1680) 2280,1680 2280,330 cw(c2130,330) 2130,180 250,180 cw(c250,330) 100,330 100,1680 cw(c250,1680)
GND on Sig1 "NONET_L01_P-001" (solid, remove dead copper, pour order 8): 250,1830 2130,1830 cw(c2130,1680) 2280,1680 2280,330 cw(c2130,330) 2130,180 250,180 cw(c250,330) 100,330 100,1680 cw(c250,1680)
GND on Bottom Layer "NONET_L01_P-001" (solid, remove dead copper, pour order 10): 250,1830 2130,1830 cw(c2130,1680) 2280,1680 2280,330 cw(c2130,330) 2130,180 250,180 cw(c250,330) 100,330 100,1680 cw(c250,1680)

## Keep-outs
Keep-Out Layer:
  the board outline again, w10

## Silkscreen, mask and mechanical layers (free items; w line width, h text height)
Top Overlay:
  drawing of 7 lines, arcs and shapes, not listed
  text "radxa/pi CM5 / INTERPOSER / Rev X5" at 2200,607.61 h45 r90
